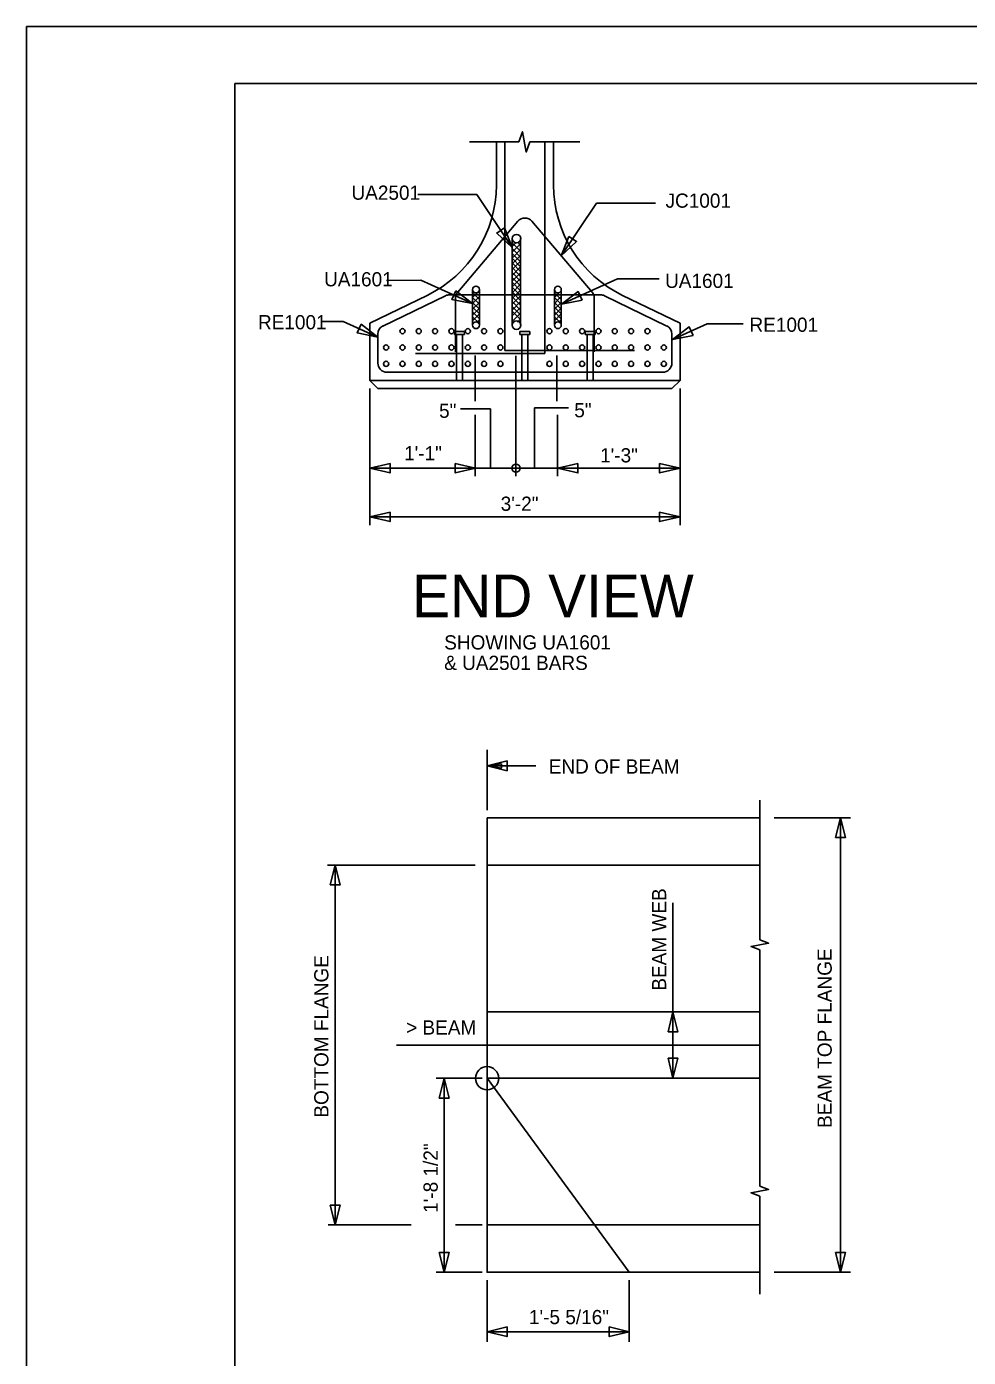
# Model space of a CAD drawing. Extents: x -55.6 to -19.5, y -5.1 to 16.9.
# Drawn here: x -55.58 to -47.29, y 5.2 to 16.91 of the extents above; entities that cross this region are included whole.
import ezdxf

# ---------------------------------------------------------------- set-up
doc = ezdxf.new("R2010")
doc.units = 0
for name, color, linetype in [('BR_AUTO DIMENSION', 7, 'Continuous'), ('BR_BORDER LINES', 7, 'Continuous'), ('BR_CENTER LINES', 7, 'Continuous'), ('BR_PRESTRESSED BEAM', 7, 'Continuous'), ('BR_REBAR', 7, 'Continuous'), ('BR_STRUCTURAL STEEL', 7, 'Continuous'), ('BR_TEXT', 7, 'Continuous'), ('Level 31', 7, 'Continuous')]:
    doc.layers.add(name, color=color, linetype=linetype)

msp = doc.modelspace()

# ---------------------------------------------------------------- linework, layer by layer
at = {"layer": 'BR_AUTO DIMENSION'}
for p, q in [((-51.621, 15.431), (-52.139, 15.431)), ((-51.621, 15.431), (-51.311, 14.966)), ((-50.567, 15.356), (-50.877, 14.891)), ((-50.567, 15.356), (-50.048, 15.356)), ((-52.416, 14.676), (-52.113, 14.677)), ((-51.659, 14.471), (-52.113, 14.677)), ((-50.876, 14.465), (-50.384, 14.688)), ((-50.016, 14.688), (-50.384, 14.688)), ((-52.978, 14.315), (-52.798, 14.315)), ((-52.493, 14.177), (-52.798, 14.315)), ((-49.898, 14.155), (-49.594, 14.294)), ((-49.278, 14.293), (-49.594, 14.294)), ((-51.636, 14.016), (-51.636, 13.612)), ((-51.277, 14.012), (-51.277, 13.192)), ((-50.917, 14.016), (-50.917, 13.612)), ((-52.563, 13.724), (-52.563, 12.523)), ((-49.832, 13.724), (-49.832, 12.523)), ((-51.501, 13.545), (-51.765, 13.545)), ((-51.636, 13.494), (-51.636, 12.952)), ((-51.501, 13.545), (-51.501, 13.024)), ((-51.112, 13.553), (-51.112, 13.024)), ((-51.112, 13.553), (-50.813, 13.553)), ((-50.911, 13.494), (-50.911, 12.952)), ((-51.277, 13.192), (-51.277, 12.952)), ((-52.563, 13.024), (-51.616, 13.024)), ((-51.616, 13.024), (-50.85, 13.024)), ((-50.85, 13.024), (-49.832, 13.024)), ((-52.563, 12.594), (-49.832, 12.594)), ((-51.53, 10.014), (-51.53, 10.546)), ((-51.101, 10.404), (-51.53, 10.404)), ((-49.13, 10.103), (-49.13, 8.872)), ((-49.004, 9.948), (-48.332, 9.948)), ((-48.42, 9.948), (-48.42, 5.948)), ((-51.635, 9.531), (-52.935, 9.531)), ((-52.868, 6.365), (-52.868, 9.531)), ((-49.895, 9.198), (-49.895, 7.656)), ((-49.13, 8.786), (-49.13, 7.791)), ((-49.13, 7.791), (-49.13, 6.706)), ((-51.575, 7.656), (-51.979, 7.656)), ((-51.908, 7.656), (-51.908, 5.948)), ((-49.13, 6.619), (-49.13, 5.757)), ((-52.2, 6.365), (-52.929, 6.365)), ((-51.598, 6.365), (-51.809, 6.365)), ((-51.574, 6.365), (-51.773, 6.365)), ((-51.575, 5.948), (-51.979, 5.948)), ((-51.53, 5.336), (-51.53, 5.878)), ((-50.28, 5.336), (-50.28, 5.878)), ((-49.004, 5.948), (-48.332, 5.948)), ((-51.53, 5.425), (-50.28, 5.425))]:
    msp.add_line(p, q, dxfattribs=at)
for points in [[(-51.376, 15.138), (-51.311, 14.966), (-51.445, 15.092)], [(-50.812, 15.063), (-50.877, 14.891), (-50.743, 15.017)], [(-51.806, 14.583), (-51.659, 14.471), (-51.84, 14.507)], [(-50.695, 14.502), (-50.876, 14.465), (-50.73, 14.577)], [(-52.639, 14.289), (-52.493, 14.177), (-52.673, 14.213)], [(-49.718, 14.192), (-49.898, 14.155), (-49.752, 14.267)], [(-52.384, 13.065), (-52.563, 13.024), (-52.384, 12.982)], [(-51.811, 13.065), (-51.632, 13.024), (-51.811, 12.982)], [(-50.731, 13.065), (-50.911, 13.024), (-50.731, 12.982)], [(-50.012, 13.065), (-49.832, 13.024), (-50.012, 12.982)], [(-52.384, 12.636), (-52.563, 12.594), (-52.384, 12.553)], [(-50.012, 12.636), (-49.832, 12.594), (-50.012, 12.553)], [(-51.355, 10.447), (-51.53, 10.404), (-51.355, 10.361)], [(-51.405, 10.422), (-51.53, 10.404), (-51.405, 10.385)], [(-48.463, 9.773), (-48.42, 9.948), (-48.377, 9.773)], [(-52.911, 9.356), (-52.868, 9.531), (-52.825, 9.356)], [(-49.938, 8.065), (-49.895, 8.24), (-49.851, 8.065)], [(-49.938, 7.831), (-49.895, 7.656), (-49.851, 7.831)], [(-51.951, 7.481), (-51.908, 7.656), (-51.865, 7.481)], [(-51.53, 7.656), (-51.53, 5.948), (-50.28, 5.948), (-51.53, 7.656)], [(-52.911, 6.54), (-52.868, 6.365), (-52.825, 6.54)], [(-51.951, 6.123), (-51.908, 5.948), (-51.865, 6.123)], [(-48.463, 6.123), (-48.42, 5.948), (-48.377, 6.123)], [(-51.355, 5.468), (-51.53, 5.425), (-51.355, 5.382)], [(-50.455, 5.468), (-50.28, 5.425), (-50.455, 5.382)]]:
    msp.add_lwpolyline(points, close=True, dxfattribs=at)
for points in [[(-49.13, 8.872), (-49.053, 8.843), (-49.207, 8.815), (-49.13, 8.786)], [(-49.13, 6.706), (-49.053, 6.677), (-49.207, 6.648), (-49.13, 6.619)]]:
    msp.add_lwpolyline(points, dxfattribs=at)
for centre, radius in [((-51.276, 13.023), 0.0359), ((-51.53, 7.656), 0.102)]:
    msp.add_circle(centre, radius, dxfattribs=at)
at = {"layer": 'BR_BORDER LINES'}
for p in [(-20.084, 16.408), (-53.75, -4.592)]:
    msp.add_line(p, (-53.75, 16.408), dxfattribs=at)
at = {"layer": 'BR_CENTER LINES'}
for p, q in [((-51.684, 15.894), (-51.252, 15.894)), ((-51.153, 15.894), (-50.715, 15.894)), ((-52.329, 7.948), (-49.13, 7.948))]:
    msp.add_line(p, q, dxfattribs=at)
msp.add_lwpolyline([(-51.252, 15.894), (-51.219, 15.983), (-51.186, 15.805), (-51.153, 15.894)], dxfattribs=at)
at = {"layer": 'BR_PRESTRESSED BEAM'}
for p, q in [((-52.563, 13.796), (-52.563, 14.299)), ((-49.832, 14.299), (-49.832, 13.796)), ((-52.563, 13.796), (-49.832, 13.796)), ((-52.456, 13.796), (-49.832, 13.796)), ((-51.53, 5.948), (-51.53, 9.948)), ((-51.53, 9.948), (-49.13, 9.948)), ((-51.53, 9.531), (-49.13, 9.531)), ((-51.53, 8.24), (-49.13, 8.24)), ((-51.53, 7.656), (-50.28, 5.948)), ((-51.53, 7.656), (-49.13, 7.656)), ((-51.53, 6.365), (-49.13, 6.365)), ((-51.53, 5.948), (-49.13, 5.948))]:
    msp.add_line(p, q, dxfattribs=at)
for points in [[(-51.449, 15.514), (-51.449, 15.894)], [(-50.946, 15.894), (-50.946, 15.514)], [(-52.563, 14.299), (-52.058, 14.543)], [(-50.338, 14.543), (-49.832, 14.299)]]:
    msp.add_lwpolyline(points, dxfattribs=at)
for centre, start, end in [((-52.527, 15.514), 295.821, 360), ((-49.868, 15.514), 180, 244.179)]:
    msp.add_arc(centre, 1.078, start, end, dxfattribs=at)
at = {"layer": 'BR_REBAR'}
for p, q in [((-51.374, 15.887), (-51.374, 14.059)), ((-51.021, 15.887), (-51.021, 14.031)), ((-51.789, 14.572), (-51.259, 15.196)), ((-50.606, 14.572), (-51.136, 15.196)), ((-51.31, 15.043), (-51.31, 14.281)), ((-51.31, 15.024), (-51.306, 15.028)), ((-51.31, 15.006), (-51.235, 14.932)), ((-51.31, 14.973), (-51.277, 15.006)), ((-51.31, 14.923), (-51.235, 14.997)), ((-51.26, 15.008), (-51.235, 14.982)), ((-51.235, 15.043), (-51.235, 14.281)), ((-51.31, 14.956), (-51.235, 14.881)), ((-51.31, 14.872), (-51.235, 14.947)), ((-51.31, 14.913), (-51.235, 14.838)), ((-51.31, 14.821), (-51.235, 14.896)), ((-51.31, 14.871), (-51.235, 14.796)), ((-51.31, 14.77), (-51.235, 14.845)), ((-51.31, 14.829), (-51.235, 14.754)), ((-51.31, 14.719), (-51.235, 14.794)), ((-51.302, 14.779), (-51.235, 14.711)), ((-51.31, 14.744), (-51.235, 14.669)), ((-51.31, 14.668), (-51.235, 14.743)), ((-51.31, 14.701), (-51.235, 14.627)), ((-51.31, 14.618), (-51.235, 14.693)), ((-51.31, 14.659), (-51.235, 14.584)), ((-51.31, 14.567), (-51.235, 14.642)), ((-51.31, 14.567), (-51.235, 14.642)), ((-52.449, 14.274), (-51.897, 14.541)), ((-51.862, 14.549), (-50.766, 14.549)), ((-51.809, 14.52), (-51.809, 14.046)), ((-51.658, 14.595), (-51.658, 14.281)), ((-51.658, 14.524), (-51.598, 14.583)), ((-51.658, 14.567), (-51.598, 14.507)), ((-51.658, 14.473), (-51.598, 14.533)), ((-51.658, 14.525), (-51.598, 14.465)), ((-50.533, 14.549), (-51.629, 14.549)), ((-51.598, 14.595), (-51.598, 14.281)), ((-51.31, 14.617), (-51.235, 14.542)), ((-51.31, 14.516), (-51.235, 14.591)), ((-51.31, 14.574), (-51.235, 14.5)), ((-51.31, 14.574), (-51.292, 14.557)), ((-51.31, 14.465), (-51.235, 14.54)), ((-51.31, 14.532), (-51.235, 14.457)), ((-50.937, 14.595), (-50.937, 14.281)), ((-50.937, 14.524), (-50.877, 14.583)), ((-50.937, 14.567), (-50.877, 14.507)), ((-50.937, 14.473), (-50.877, 14.533)), ((-50.937, 14.525), (-50.877, 14.465)), ((-50.877, 14.595), (-50.877, 14.281)), ((-50.587, 14.52), (-50.587, 14.046)), ((-49.947, 14.274), (-50.498, 14.541)), ((-51.658, 14.422), (-51.598, 14.482)), ((-51.658, 14.482), (-51.598, 14.422)), ((-51.658, 14.44), (-51.598, 14.38)), ((-51.658, 14.371), (-51.598, 14.431)), ((-51.31, 14.49), (-51.235, 14.415)), ((-51.31, 14.414), (-51.235, 14.489)), ((-51.31, 14.447), (-51.235, 14.373)), ((-51.31, 14.364), (-51.235, 14.438)), ((-51.31, 14.405), (-51.235, 14.33)), ((-50.937, 14.422), (-50.877, 14.482)), ((-50.937, 14.482), (-50.877, 14.422)), ((-50.937, 14.44), (-50.877, 14.38)), ((-50.937, 14.371), (-50.877, 14.431)), ((-51.658, 14.398), (-51.598, 14.338)), ((-51.658, 14.32), (-51.598, 14.38)), ((-51.658, 14.355), (-51.598, 14.295)), ((-51.658, 14.313), (-51.648, 14.303)), ((-51.618, 14.309), (-51.598, 14.329)), ((-51.31, 14.313), (-51.235, 14.388)), ((-51.263, 14.309), (-51.235, 14.337)), ((-50.937, 14.398), (-50.877, 14.338)), ((-50.937, 14.32), (-50.877, 14.38)), ((-50.937, 14.355), (-50.877, 14.295)), ((-50.937, 14.313), (-50.927, 14.303)), ((-50.897, 14.309), (-50.877, 14.329)), ((-52.491, 13.948), (-52.491, 14.206)), ((-49.904, 13.948), (-49.904, 14.206)), ((-51.374, 14.059), (-50.234, 14.059)), ((-51.021, 14.031), (-52.161, 14.031)), ((-52.411, 13.868), (-50.766, 13.868)), ((-49.985, 13.868), (-51.629, 13.868))]:
    msp.add_line(p, q, dxfattribs=at)
for centre, radius in [((-51.272, 15.043), 0.0374), ((-51.628, 14.595), 0.0299), ((-50.907, 14.595), 0.0299), ((-51.628, 14.281), 0.0299), ((-51.272, 14.281), 0.0374), ((-50.907, 14.281), 0.0299), ((-52.275, 14.229), 0.0225), ((-52.132, 14.229), 0.0225), ((-51.988, 14.229), 0.0225), ((-51.844, 14.229), 0.0225), ((-51.7, 14.229), 0.0225), ((-51.557, 14.229), 0.0225), ((-51.413, 14.229), 0.0225), ((-50.982, 14.229), 0.0225), ((-50.838, 14.229), 0.0225), ((-50.694, 14.229), 0.0225), ((-50.55, 14.229), 0.0225), ((-50.407, 14.229), 0.0225), ((-50.263, 14.229), 0.0225), ((-50.119, 14.229), 0.0225), ((-52.419, 14.085), 0.0225), ((-52.275, 14.085), 0.0225), ((-52.132, 14.085), 0.0225), ((-51.988, 14.085), 0.0225), ((-51.844, 14.085), 0.0225), ((-51.7, 14.085), 0.0225), ((-51.557, 14.085), 0.0225), ((-51.413, 14.085), 0.0225), ((-50.982, 14.085), 0.0225), ((-50.838, 14.085), 0.0225), ((-50.694, 14.085), 0.0225), ((-50.55, 14.085), 0.0225), ((-50.407, 14.085), 0.0225), ((-50.263, 14.085), 0.0225), ((-50.119, 14.085), 0.0225), ((-49.975, 14.085), 0.0225), ((-52.419, 13.941), 0.0225), ((-52.275, 13.941), 0.0225), ((-52.132, 13.941), 0.0225), ((-51.988, 13.941), 0.0225), ((-51.844, 13.941), 0.0225), ((-51.7, 13.941), 0.0225), ((-51.557, 13.941), 0.0225), ((-51.413, 13.941), 0.0225), ((-50.982, 13.941), 0.0225), ((-50.838, 13.941), 0.0225), ((-50.694, 13.941), 0.0225), ((-50.55, 13.941), 0.0225), ((-50.407, 13.941), 0.0225), ((-50.263, 13.941), 0.0225), ((-50.119, 13.941), 0.0225), ((-49.975, 13.941), 0.0225)]:
    msp.add_circle(centre, radius, dxfattribs=at)
for centre, start, end in [((-51.198, 15.143), 40.3646, 139.6354), ((-51.862, 14.468), 90, 115.821), ((-51.728, 14.52), 139.6354, 180), ((-50.668, 14.52), 360, 40.3646), ((-50.533, 14.468), 64.179, 90), ((-52.411, 14.203), 115.821, 180), ((-49.985, 14.203), 360, 64.179), ((-52.411, 13.948), 180, 270), ((-49.985, 13.948), 270, 360)]:
    msp.add_arc(centre, 0.0809, start, end, dxfattribs=at)
at = {"layer": 'BR_STRUCTURAL STEEL'}
for p, q in [((-51.818, 14.227), (-51.728, 14.227)), ((-51.818, 14.2), (-51.818, 14.227)), ((-51.818, 14.2), (-51.728, 14.2)), ((-51.8, 13.796), (-51.8, 14.2)), ((-51.746, 13.796), (-51.746, 14.2)), ((-51.728, 14.2), (-51.728, 14.227)), ((-51.243, 14.227), (-51.153, 14.227)), ((-51.243, 14.2), (-51.243, 14.227)), ((-51.243, 14.2), (-51.153, 14.2)), ((-51.225, 13.796), (-51.225, 14.2)), ((-51.171, 13.796), (-51.171, 14.2)), ((-51.153, 14.2), (-51.153, 14.227)), ((-50.668, 14.227), (-50.578, 14.227)), ((-50.668, 14.2), (-50.668, 14.227)), ((-50.668, 14.2), (-50.578, 14.2)), ((-50.65, 13.796), (-50.65, 14.2)), ((-50.596, 13.796), (-50.596, 14.2)), ((-50.578, 14.2), (-50.578, 14.227)), ((-52.491, 13.724), (-52.563, 13.796)), ((-52.491, 13.724), (-49.904, 13.724)), ((-49.904, 13.724), (-49.832, 13.796))]:
    msp.add_line(p, q, dxfattribs=at)
at = {"layer": 'Level 31'}
msp.add_lwpolyline([(-55.583, -5.092), (-19.583, -5.092), (-19.583, 16.908), (-55.583, 16.908)], close=True, dxfattribs=at)

# ---------------------------------------------------------------- texts
at = {"layer": 'BR_AUTO DIMENSION'}
for s, p in [('BEAM WEB', (-49.954, 8.426)), ('BEAM TOP FLANGE', (-48.497, 7.219)), ('BOTTOM FLANGE', (-52.927, 7.309)), ('1\'-8 1/2"', (-51.965, 6.471))]:
    msp.add_text(s, height=0.125, rotation=90, dxfattribs=at).set_placement(p)
msp.add_text('1\'-5 5/16"', height=0.125, dxfattribs=at).set_placement((-51.162, 5.492))
at = {"layer": 'BR_TEXT'}
for s, height, p in [('UA2501', 0.125, (-52.724, 15.385)), ('JC1001', 0.125, (-49.96, 15.315)), ('UA1601', 0.125, (-52.965, 14.623)), ('UA1601', 0.125, (-49.964, 14.609)), ('RE1001', 0.125, (-53.547, 14.245)), ('RE1001', 0.125, (-49.221, 14.223)), ('5"', 0.125, (-51.953, 13.466)), ('5"', 0.125, (-50.763, 13.471)), ('1\'-1"', 0.125, (-52.261, 13.092)), ('1\'-3"', 0.125, (-50.536, 13.074)), ('3\'-2"', 0.125, (-51.411, 12.648)), ('END VIEW', 0.375, (-52.191, 11.712)), ('SHOWING UA1601', 0.125, (-51.908, 11.428)), ('& UA2501 BARS', 0.125, (-51.908, 11.248)), ('END OF BEAM', 0.125, (-50.988, 10.336))]:
    msp.add_text(s, height=height, dxfattribs=at).set_placement(p)
msp.add_text('> BEAM', height=0.125, rotation=360, dxfattribs=at).set_placement((-52.243, 8.04))

doc.saveas('drawing.dxf')
